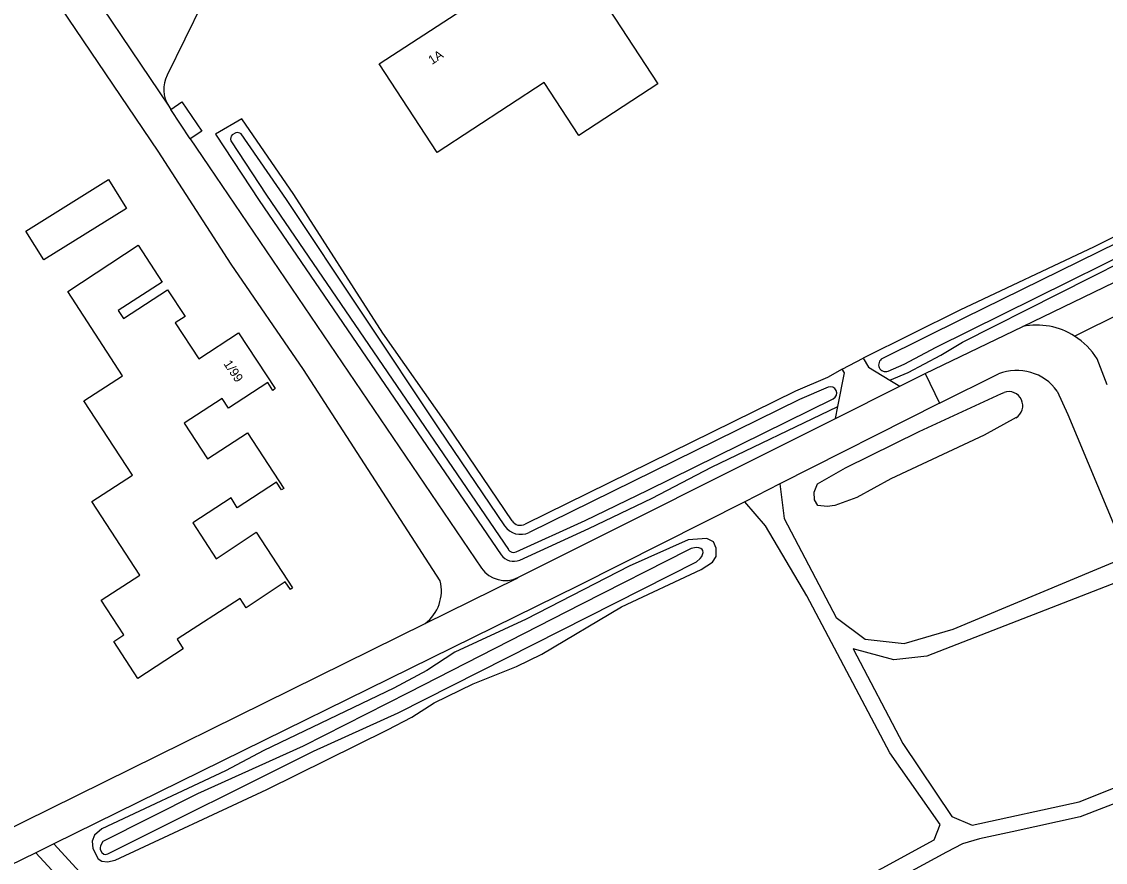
# Model space of a CAD drawing. Extents: x 162791 to 163827, y 385795 to 386523.
# Drawn here: x 163143.1 to 163263.1, y 386320.2 to 386413.4 of the extents above; entities that cross this region are included whole.
import ezdxf

# ---------------------------------------------------------------- set-up
doc = ezdxf.new("R2010")
doc.units = 0
for name, color, linetype in [('IMGEO_Erf', 7, 'Continuous'), ('IMGEO_Gemengd_bos', 7, 'Continuous'), ('IMGEO_Pand', 7, 'Continuous'), ('IMGEO_Pand_nummerreeks', 7, 'Continuous'), ('IMGEO_Pand_vergunning_verleend', 7, 'Continuous'), ('IMGEO_Voetpad_halfverhard', 7, 'Continuous'), ('IMGEO_Voetpad_open', 7, 'Continuous'), ('IMGEO_Waterloop', 7, 'Continuous'), ('IMGEO_Woonerf_open', 7, 'Continuous')]:
    doc.layers.add(name, color=color, linetype=linetype)

msp = doc.modelspace()

# ---------------------------------------------------------------- linework, layer by layer
at = {"layer": 'IMGEO_Erf'}
for points in [[(163239.27, 386373.67), (163241.29, 386374.54), (163244.91, 386376.46), (163247.33, 386377.88), (163268.68, 386388.68), (163278.12, 386392.91), (163309.16, 386408.83), (163310.16, 386409.79), (163310.54, 386410.75), (163310.52, 386411.49), (163310.26, 386411.93), (163309.6, 386412.05), (163308.1, 386411.77), (163306.5, 386411.23), (163304.5, 386410.04), (163291.96, 386403.48), (163285.34, 386400.29), (163261.91, 386388.47), (163247.03, 386381.44), (163236.33, 386376.13)], [(163197.45, 386358.09), (163190.19, 386368.84), (163183.14, 386378.9), (163173.28, 386394.26), (163167.5, 386402.64), (163164.58, 386400.96), (163169.41, 386393.61), (163196.21, 386354.34)], [(163234.01, 386374.89), (163232.38, 386373.97), (163228.84, 386372.45), (163198.88, 386357.71)], [(163198.3, 386353.75), (163205.94, 386357.23), (163212.94, 386360.6), (163219.54, 386364.04), (163233.53, 386370.77)]]:
    msp.add_lwpolyline(points, dxfattribs=at)
for centre, radius, start, end in [((163198.38, 386358.72), 1.13, 213.9935, 296.382), ((163197.6, 386355.28), 1.68, 214.2495, 294.4272)]:
    msp.add_arc(centre, radius, start, end, dxfattribs=at)
at = {"layer": 'IMGEO_Gemengd_bos'}
msp.add_lwpolyline([(163200.74, 386343.3), (163209.54, 386348.55), (163218.39, 386352.7), (163219.65, 386353.5), (163220.04, 386354.14), (163220.05, 386355.08), (163219.76, 386355.76), (163219.02, 386356.12), (163216.94, 386355.98), (163210.42, 386353.07), (163198.98, 386347.2), (163191.08, 386343.52), (163188.01, 386341.51), (163184.33, 386339.55), (163169.95, 386332.64), (163165.69, 386330.39), (163151.98, 386323.94), (163151.2, 386323.26), (163150.92, 386322.58), (163151, 386321.78), (163151.58, 386320.62), (163151.98, 386320.36), (163152.64, 386320.3), (163153.46, 386320.5), (163170.27, 386328.3), (163183.63, 386334.93), (163186.33, 386336.35), (163188.82, 386337.91), (163193.12, 386340.02), (163197.94, 386341.96), (163200.74, 386343.3)], dxfattribs=at)
at = {"layer": 'IMGEO_Pand'}
for points in [[(163202.72, 386423.13), (163213.57, 386406.51), (163204.83, 386400.81), (163201, 386406.67), (163189.13, 386398.92), (163182.73, 386408.73), (163191.99, 386414.77)], [(163151.91, 386349.29), (163156.19, 386352.07), (163150.89, 386360.23), (163155.38, 386363.14), (163150.02, 386371.39), (163154.3, 386374.16), (163148.22, 386383.52), (163156.04, 386388.64), (163158.69, 386384.56), (163153.82, 386381.4), (163154.38, 386380.52), (163159.29, 386383.69), (163161.21, 386380.74), (163160.11, 386380.03), (163162.75, 386376.04), (163167.13, 386378.92), (163171.18, 386372.74), (163170.95, 386372.55), (163170.37, 386373.43), (163166.01, 386370.57), (163165.33, 386371.66), (163161.12, 386368.93), (163163.7, 386364.96), (163168.14, 386367.86), (163172.15, 386361.69), (163171.9, 386361.54), (163171.36, 386362.38), (163166.98, 386359.52), (163166.31, 386360.63), (163162.07, 386357.88), (163164.66, 386353.89), (163169.1, 386356.82), (163173.12, 386350.66), (163172.89, 386350.49), (163172.32, 386351.34), (163167.97, 386348.46), (163167.31, 386349.49), (163160.34, 386344.96), (163161.02, 386343.91), (163155.97, 386340.63), (163153.32, 386344.72), (163154.42, 386345.44), (163151.91, 386349.29)]]:
    msp.add_lwpolyline(points, dxfattribs=at)
at = {"layer": 'IMGEO_Pand_vergunning_verleend'}
msp.add_lwpolyline([(163143.58, 386390.2), (163152.73, 386395.92), (163154.73, 386392.72), (163145.58, 386387), (163143.58, 386390.2)], dxfattribs=at)
at = {"layer": 'IMGEO_Voetpad_halfverhard'}
for points in [[(163253.99, 386379.64), (163312.42, 386407.89)], [(163259.74, 386378.56), (163319.5, 386408.26)], [(163227.11, 386362.18), (163223.2, 386360.2)], [(163227.11, 386362.18), (163227.57, 386358.35), (163233.34, 386347.39), (163236.53, 386344.99), (163240.87, 386344.48), (163246.3, 386346.08), (163265.57, 386354.14)], [(163146.68, 386322.3), (163163.05, 386304.46), (163174.71, 386298.21), (163176.62, 386297.32), (163178.56, 386296.51), (163181.4, 386295.62), (163182.61, 386295.4), (163184.73, 386295.24), (163187.04, 386295.46), (163188.87, 386295.91), (163216.32, 386307.39), (163221.54, 386310.39), (163244.17, 386322.73), (163244.86, 386324.42), (163239.28, 386332.37), (163230.09, 386349.78), (163225.52, 386357.53), (163223.2, 386360.2)], [(163266.44, 386352.07), (163243.38, 386343.1), (163239.73, 386342.7), (163235.22, 386343.9), (163240.7, 386333.43), (163246.13, 386325.33), (163248.41, 386324.36), (163260.26, 386326.94), (163274.51, 386332.65)], [(163275.88, 386331.29), (163260.37, 386325.29), (163252.83, 386323.64), (163249.2, 386322.85), (163247.32, 386322.31), (163245.56, 386321.36), (163220.43, 386307.74), (163217.35, 386306.13), (163191.76, 386295.05), (163188.1, 386294.14), (163185.1, 386293.41), (163183.89, 386293.36), (163181.73, 386293.63), (163179.14, 386294.37), (163177.56, 386294.94), (163175.56, 386295.74), (163173.59, 386296.58), (163161.79, 386302.75), (163144.67, 386321.31)], [(163146.68, 386322.3), (163144.67, 386321.31)]]:
    msp.add_lwpolyline(points, dxfattribs=at)
msp.add_arc((163255.52, 386371.92), 7.87, 57.5512, 101.1962, dxfattribs=at)
at = {"layer": 'IMGEO_Voetpad_open'}
for points in [[(163176.85, 386443.41), (163159.22, 386407.47)], [(163147.85, 386421.24), (163159.42, 386404.03)], [(163159.64, 386403.68), (163160.87, 386404.53), (163163.06, 386401.27), (163161.79, 386400.43)], [(163161.79, 386400.43), (163159.64, 386403.68)], [(163234.01, 386374.89), (163236.33, 386376.13)], [(163236.33, 386376.13), (163236.92, 386375.11), (163239.27, 386373.67)], [(163233.53, 386370.77), (163234.25, 386374.48), (163234.01, 386374.89)], [(163233.27, 386369.45), (163240.37, 386373.01)], [(163239.27, 386373.67), (163240.37, 386373.01)], [(163233.27, 386369.45), (163233.53, 386370.77)]]:
    msp.add_lwpolyline(points, dxfattribs=at)
msp.add_arc((163162.36, 386405.93), 3.5, 153.8321, 212.7602, dxfattribs=at)
at = {"layer": 'IMGEO_Waterloop'}
for points in [[(163308.66, 386410.86), (163308.35, 386410.8), (163306.92, 386410.32), (163285.79, 386399.39), (163247.47, 386380.54), (163238.46, 386376.07)], [(163239.1, 386374.69), (163240.86, 386375.44), (163244.42, 386377.33), (163277.69, 386393.82), (163308.57, 386409.66), (163309.04, 386410.11)], [(163166.28, 386400.2), (163170.24, 386394.17), (163197.04, 386354.9)], [(163166.84, 386401.11), (163166.44, 386400.88)], [(163196.62, 386357.53), (163189.37, 386368.27), (163172.45, 386393.71), (163167.43, 386400.97)], [(163232.43, 386372.9), (163229.26, 386371.54), (163199.32, 386356.81)], [(163197.88, 386354.66), (163205.52, 386358.14), (163212.49, 386361.5), (163233.01, 386371.63)], [(163249.73, 386367.6), (163239.39, 386362.73), (163235.63, 386360.67), (163233.19, 386359.79), (163232.32, 386359.69), (163231.31, 386359.79), (163230.93, 386360.43), (163230.89, 386361.27), (163231.25, 386362.21), (163234.35, 386363.97), (163242.51, 386368), (163251.65, 386372.2), (163251.93, 386372.33)], [(163253.26, 386369.53), (163249.73, 386367.6)], [(163217.85, 386353.55), (163218.28, 386353.91), (163218.46, 386354.15), (163218.61, 386354.57), (163218.57, 386354.81), (163218.5, 386354.91), (163218.33, 386355.03), (163218.12, 386355.1), (163217.81, 386355.14), (163217.27, 386355.02), (163216.9, 386354.84), (163205.14, 386348.84), (163185.93, 386339.04), (163174.3, 386333.11), (163162.61, 386327.82), (163152.1, 386322.56), (163151.86, 386322.08), (163151.81, 386321.84), (163151.83, 386321.67), (163151.98, 386321.33), (163152.22, 386321.15), (163152.42, 386321.13), (163152.68, 386321.18), (163175.44, 386332.58), (163184.83, 386336.8), (163217.85, 386353.55)]]:
    msp.add_lwpolyline(points, dxfattribs=at)
for centre, radius, start, end in [((163166.99, 386400.39), 0.738, 138.1945, 195.194), ((163166.99, 386400.39), 0.735, 52.6278, 101.9294), ((163238.8, 386375.39), 0.762, 116.4377, 293.1914), ((163232.71, 386372.26), 0.7, 295.6804, 113.2007), ((163252.44, 386370.85), 1.56, 301.6346, 109.1649), ((163198.38, 386358.72), 2.13, 213.9686, 296.2003), ((163197.6, 386355.28), 0.681, 214.3174, 294.2772)]:
    msp.add_arc(centre, radius, start, end, dxfattribs=at)
at = {"layer": 'IMGEO_Woonerf_open'}
for points in [[(163189.47, 386351.45), (163174.34, 386374.85), (163166.31, 386386.55), (163158.23, 386399.07), (163142.49, 386422.41)], [(163159.42, 386404.03), (163159.64, 386403.68)], [(163161.79, 386400.43), (163194.06, 386352.86)], [(163243.18, 386374.41), (163253.99, 386379.64)], [(163263.34, 386373.16), (163262.23, 386376.04)], [(163240.37, 386373.01), (163243.18, 386374.41)], [(163243.18, 386374.41), (163244.77, 386371.12)], [(163244.77, 386371.12), (163251.31, 386374.37)], [(163257.81, 386372.46), (163258.98, 386369.88), (163265.57, 386354.14)], [(163244.77, 386371.12), (163227.11, 386362.18)], [(163198.08, 386351.82), (163233.27, 386369.45)], [(163223.2, 386360.2), (163204.76, 386350.87), (163146.68, 386322.3)], [(163187.8, 386346.71), (163197.93, 386351.71), (163198.08, 386351.82)], [(163130.32, 386318.97), (163130.52, 386318.93), (163130.74, 386318.9), (163130.95, 386318.89), (163131.17, 386318.9), (163131.38, 386318.93), (163131.59, 386318.97), (163131.8, 386319.04), (163132, 386319.12), (163132.19, 386319.21), (163137.37, 386321.83), (163187.8, 386346.71)], [(163144.67, 386321.31), (163140.19, 386319.11), (163136.75, 386317.37), (163136.67, 386317.32), (163136.6, 386317.26), (163136.53, 386317.19), (163136.46, 386317.11), (163136.4, 386317.04), (163136.36, 386316.95), (163136.31, 386316.86), (163136.28, 386316.77), (163136.25, 386316.68), (163136.24, 386316.58), (163136.23, 386316.49), (163136.22, 386316.39), (163136.23, 386316.29), (163136.25, 386316.2), (163136.27, 386316.1), (163136.3, 386316.01), (163136.34, 386315.92), (163136.86, 386314.98)]]:
    msp.add_lwpolyline(points, dxfattribs=at)
for centre, radius, start, end in [((163255.51, 386371.9), 7.89, 31.5893, 57.542), ((163253.34, 386369.28), 5.49, 35.4174, 111.7234), ((163196.67, 386354.64), 3.16, 214.3208, 296.6637), ((163185.11, 386350.32), 4.5, 306.6921, 14.4455)]:
    msp.add_arc(centre, radius, start, end, dxfattribs=at)

# ---------------------------------------------------------------- texts
at = {"layer": 'IMGEO_Pand_nummerreeks'}
for s, rotation, p in [('1A', 33.137, (163188.56, 386408.61)), ('1/99', 303.9202, (163165.44, 386375.5))]:
    msp.add_text(s, height=1, rotation=rotation, dxfattribs=at).set_placement(p)

doc.saveas('drawing.dxf')
